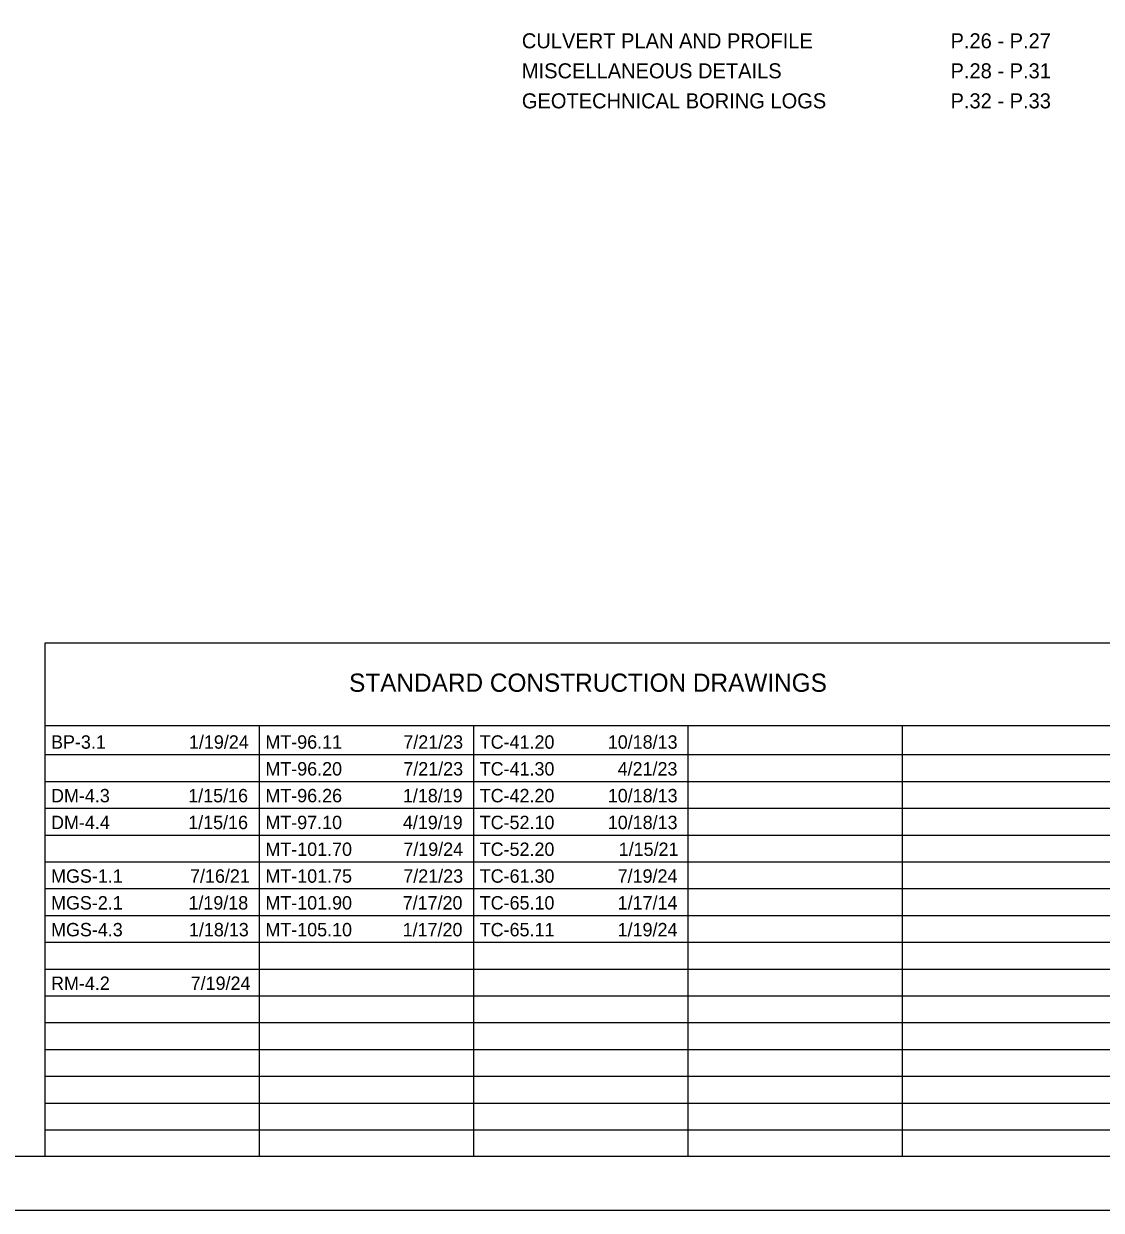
# Model space of a CAD drawing. Extents: x -3.3 to 34, y 0 to 56.8.
# Drawn here: x 9.95 to 20, y 0 to 11.07 of the extents above; entities that cross this region are included whole.
import ezdxf

# ---------------------------------------------------------------- set-up
doc = ezdxf.new("R2010")
doc.units = 0
for name, color, linetype in [('SH_Border', 7, 'Continuous'), ('SH_Cut_Line', 7, 'Continuous'), ('SH_Data', 7, 'Continuous'), ('SH_Major_Grid_Line', 7, 'Continuous')]:
    doc.layers.add(name, color=color, linetype=linetype)

msp = doc.modelspace()

# ---------------------------------------------------------------- linework, layer by layer
at = {"layer": 'SH_Border'}
msp.add_lwpolyline([(0, 0), (34, 0), (34, 22), (0, 22)], close=True, dxfattribs=at)
at = {"layer": 'SH_Cut_Line'}
msp.add_lwpolyline([(1.5, 21.5), (33.5, 21.5), (33.5, 0.5), (1.5, 0.5)], close=True, dxfattribs=at)
at = {"layer": 'SH_Data'}
for p, q in [((10.15, 5.292), (23.6, 5.292)), ((10.15, 0.5), (10.15, 5.292)), ((10.15, 4.521), (23.6, 4.521)), ((12.15, 0.5), (12.15, 4.521)), ((14.15, 0.5), (14.15, 4.521)), ((16.15, 0.5), (16.15, 4.521)), ((18.15, 0.5), (18.15, 4.521)), ((10.15, 4.25), (23.6, 4.25)), ((10.15, 4), (23.6, 4)), ((10.15, 3.75), (23.6, 3.75)), ((10.15, 3.5), (23.6, 3.5)), ((10.15, 3.25), (23.6, 3.25)), ((10.15, 3), (23.6, 3)), ((10.15, 2.75), (23.6, 2.75)), ((10.15, 2.5), (23.6, 2.5)), ((10.15, 2.25), (23.6, 2.25)), ((10.15, 2), (23.6, 2)), ((10.15, 1.75), (23.6, 1.75)), ((10.15, 1.5), (23.6, 1.5)), ((10.15, 1.25), (23.6, 1.25)), ((10.15, 1), (23.6, 1)), ((10.15, 0.75), (23.6, 0.75))]:
    msp.add_line(p, q, dxfattribs=at)

# ---------------------------------------------------------------- texts
at = {"layer": 'SH_Major_Grid_Line'}
for s, height, p in [('CULVERT PLAN AND PROFILE           ', 0.14, (14.598, 10.838)), ('P.26 - P.27', 0.14, (18.598, 10.838)), ('MISCELLANEOUS DETAILS              ', 0.14, (14.598, 10.558)), ('P.28 - P.31', 0.14, (18.598, 10.558)), ('GEOTECHNICAL BORING LOGS           ', 0.14, (14.598, 10.278)), ('P.32 - P.33', 0.14, (18.598, 10.278)), ('STANDARD CONSTRUCTION DRAWINGS', 0.17, (12.986, 4.836)), ('BP-3.1', 0.125, (10.205, 4.305)), ('1/19/24', 0.125, (11.492, 4.305)), ('MT-96.11', 0.125, (12.205, 4.305)), ('7/21/23', 0.125, (13.492, 4.305)), ('TC-41.20', 0.125, (14.205, 4.305)), ('10/18/13', 0.125, (15.4, 4.305)), ('MT-96.20', 0.125, (12.205, 4.055)), ('7/21/23', 0.125, (13.492, 4.055)), ('TC-41.30', 0.125, (14.205, 4.055)), ('4/21/23', 0.125, (15.492, 4.055)), ('DM-4.3', 0.125, (10.205, 3.805)), ('1/15/16', 0.125, (11.485, 3.805)), ('MT-96.26', 0.125, (12.205, 3.805)), ('1/18/19', 0.125, (13.488, 3.805)), ('TC-42.20', 0.125, (14.205, 3.805)), ('10/18/13', 0.125, (15.4, 3.805)), ('DM-4.4', 0.125, (10.205, 3.555)), ('1/15/16', 0.125, (11.485, 3.555)), ('MT-97.10', 0.125, (12.205, 3.555)), ('4/19/19', 0.125, (13.488, 3.555)), ('TC-52.10', 0.125, (14.205, 3.555)), ('10/18/13', 0.125, (15.4, 3.555)), ('MT-101.70', 0.125, (12.205, 3.305)), ('7/19/24', 0.125, (13.492, 3.305)), ('TC-52.20', 0.125, (14.205, 3.305)), ('1/15/21', 0.125, (15.502, 3.305)), ('MGS-1.1', 0.125, (10.205, 3.055)), ('7/16/21', 0.125, (11.502, 3.055)), ('MT-101.75', 0.125, (12.205, 3.055)), ('7/21/23', 0.125, (13.492, 3.055)), ('TC-61.30', 0.125, (14.205, 3.055)), ('7/19/24', 0.125, (15.492, 3.055)), ('MGS-2.1', 0.125, (10.205, 2.805)), ('1/19/18', 0.125, (11.487, 2.805)), ('MT-101.90', 0.125, (12.205, 2.805)), ('7/17/20', 0.125, (13.486, 2.805)), ('TC-65.10', 0.125, (14.205, 2.805)), ('1/17/14', 0.125, (15.492, 2.805)), ('MGS-4.3', 0.125, (10.205, 2.555)), ('1/18/13', 0.125, (11.492, 2.555)), ('MT-105.10', 0.125, (12.205, 2.555)), ('1/17/20', 0.125, (13.486, 2.555)), ('TC-65.11', 0.125, (14.205, 2.555)), ('1/19/24', 0.125, (15.492, 2.555)), ('RM-4.2', 0.125, (10.205, 2.055)), ('7/19/24', 0.125, (11.508, 2.055))]:
    msp.add_text(s, height=height, dxfattribs=at).set_placement(p)

doc.saveas('drawing.dxf')
